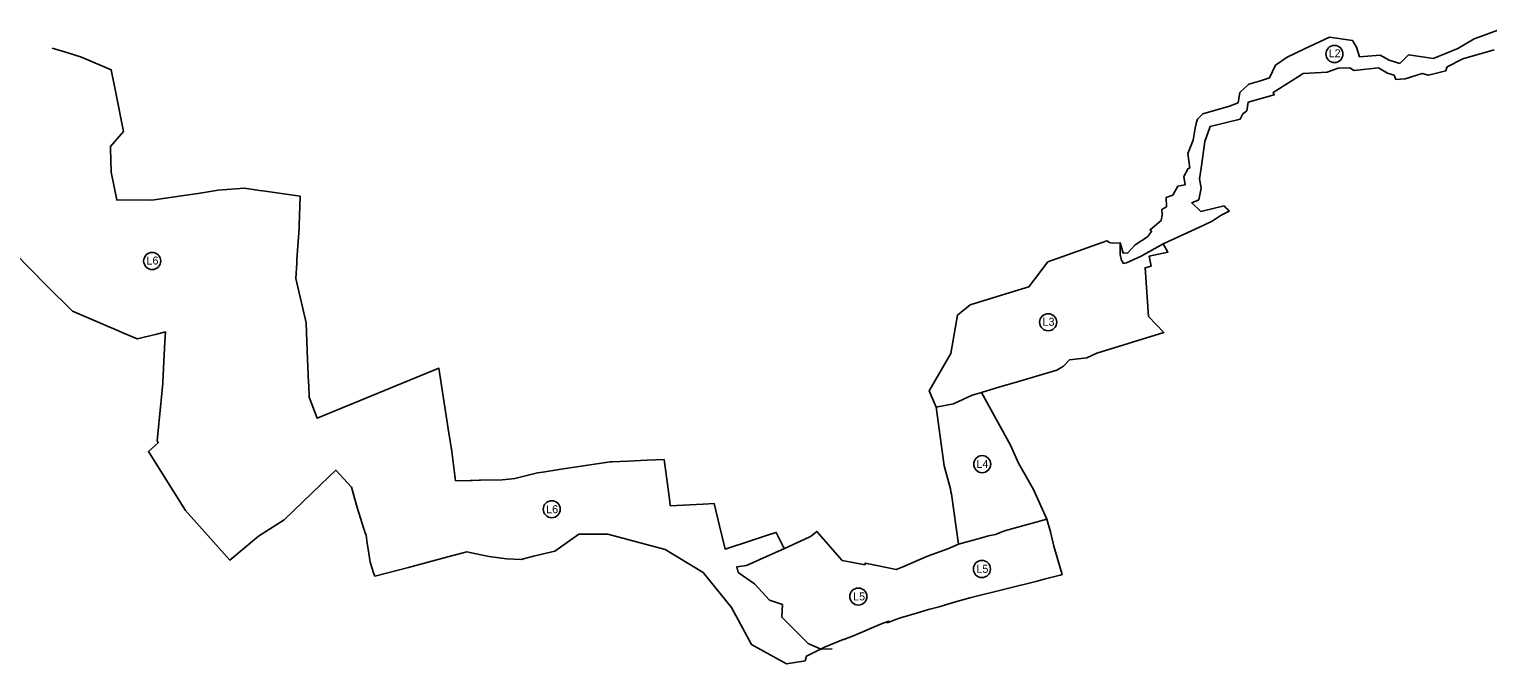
# Model space of a CAD drawing. Extents: x -445081 to -429827, y -1135509 to -1130100.
# Drawn here: x -443832 to -441644, y -1133014 to -1132062 of the extents above; entities that cross this region are included whole.
import ezdxf

# ---------------------------------------------------------------- set-up
doc = ezdxf.new("R2010")
doc.units = 0
for name, color, linetype in [('Vrstva 32', 7, 'Continuous'), ('Vrstva 33', 7, 'Continuous'), ('Vrstva 36', 7, 'Continuous')]:
    doc.layers.add(name, color=color, linetype=linetype)

msp = doc.modelspace()

# ---------------------------------------------------------------- linework, layer by layer
at = {"layer": 'Vrstva 32'}
for points in [[(-442481.7, -1132604.5), (-442471.3, -1132628.9), (-442445, -1132624.2), (-442417, -1132611.1), (-442403.3, -1132606.9), (-442375.6, -1132598.5), (-442355.9, -1132592.9), (-442352.4, -1132591.8), (-442289.9, -1132573.6), (-442280.2, -1132567.3), (-442271.2, -1132557.9), (-442244.9, -1132555), (-442229.9, -1132548), (-442129.4, -1132516.8), (-442152.4, -1132493.2), (-442157.6, -1132419.9), (-442148.6, -1132417.3), (-442151.5, -1132402.4), (-442123.4, -1132396.4), (-442130.5, -1132383.9), (-442163.5, -1132402.4), (-442185.4, -1132412.5), (-442190.7, -1132413.5), (-442190.7, -1132412.2), (-442193.2, -1132409.2), (-442195.3, -1132400), (-442195.2, -1132382.4), (-442206.9, -1132383.1), (-442211.2, -1132381.9), (-442215.2, -1132379.6), (-442303.5, -1132411.2), (-442331.9, -1132448.3), (-442353.4, -1132454.8), (-442420.1, -1132475.6), (-442439.3, -1132491), (-442442.6, -1132510.8), (-442449, -1132548.5), (-442481.7, -1132604.5)], [(-442285.2, -1132881.1), (-442281.9, -1132880.2), (-442294.6, -1132837.7), (-442299.5, -1132816), (-442304.9, -1132797), (-442368.8, -1132814.3), (-442381.9, -1132819.8), (-442392.6, -1132822.1), (-442404.6, -1132825.4), (-442437.4, -1132834.6), (-442453.6, -1132841.4), (-442484, -1132852.3), (-442499.3, -1132858.8), (-442519.7, -1132867.8), (-442531, -1132872.7), (-442562.6, -1132866.1), (-442577.8, -1132862.9), (-442577.7, -1132865.3), (-442612, -1132859.2), (-442612.8, -1132858.5), (-442649.9, -1132815.5), (-442657.9, -1132821.9), (-442661.6, -1132824.2), (-442698.6, -1132841), (-442735.4, -1132857.5), (-442755.4, -1132866.7), (-442770, -1132868.5), (-442768.2, -1132877), (-442743.8, -1132894.2), (-442720.9, -1132918.3), (-442701.6, -1132925.2), (-442702.7, -1132943.8), (-442663.1, -1132983.6), (-442643.9, -1132991.8), (-442643.5, -1132991.5), (-442639.5, -1132989.6), (-442638.7, -1132989.2), (-442610.4, -1132977.7), (-442609.9, -1132977.5), (-442609.4, -1132977.3), (-442596.7, -1132972.3), (-442581.2, -1132965.8), (-442568.4, -1132960.4), (-442553.3, -1132954.2), (-442551.9, -1132953.7), (-442542.3, -1132949.9), (-442544.6, -1132952.4), (-442540.7, -1132951), (-442532.9, -1132947.8), (-442524.4, -1132945.2), (-442497.2, -1132936.8), (-442487.8, -1132934.2), (-442480.6, -1132932.2), (-442466.4, -1132928.3), (-442445.5, -1132922.1), (-442420.8, -1132914.9), (-442364.2, -1132900.9), (-442319.8, -1132890.2), (-442309.1, -1132886.8), (-442285.2, -1132881.1)], [(-442281.9, -1132880.2), (-442294.6, -1132837.7), (-442299.5, -1132816), (-442304.9, -1132797), (-442368.8, -1132814.3), (-442381.9, -1132819.8), (-442392.6, -1132822.1), (-442404.6, -1132825.4), (-442437.4, -1132834.6), (-442453.6, -1132841.4), (-442484, -1132852.3), (-442499.3, -1132858.8), (-442519.7, -1132867.8), (-442531, -1132872.7), (-442562.6, -1132866.1), (-442577.8, -1132862.9), (-442577.7, -1132865.3), (-442612, -1132859.2), (-442612.8, -1132858.5), (-442649.9, -1132815.5), (-442657.9, -1132821.9), (-442661.6, -1132824.2), (-442698.6, -1132841), (-442735.4, -1132857.5), (-442755.4, -1132866.7), (-442770, -1132868.5), (-442768.2, -1132877), (-442743.8, -1132894.2), (-442720.9, -1132918.3), (-442701.6, -1132925.2), (-442702.7, -1132943.8), (-442663.1, -1132983.6), (-442643.9, -1132991.8), (-442627.1, -1132991.7)]]:
    msp.add_lwpolyline(points, dxfattribs=at)
msp.add_lwpolyline([(-442471.3, -1132628.9), (-442445, -1132624.2), (-442417, -1132611.1), (-442403.3, -1132606.9), (-442375.6, -1132598.5), (-442355.9, -1132592.9), (-442352.4, -1132591.8), (-442289.9, -1132573.6), (-442280.2, -1132567.3), (-442271.2, -1132557.9), (-442244.9, -1132555), (-442229.9, -1132548), (-442129.4, -1132516.8), (-442152.4, -1132493.2), (-442157.6, -1132419.9), (-442148.6, -1132417.3), (-442151.5, -1132402.4), (-442123.4, -1132396.4), (-442130.5, -1132383.9), (-442163.5, -1132402.4), (-442185.4, -1132412.5), (-442190.7, -1132413.5), (-442190.7, -1132412.2), (-442193.2, -1132409.2), (-442195.3, -1132400), (-442195.2, -1132382.4), (-442206.9, -1132383.1), (-442211.2, -1132381.9), (-442215.2, -1132379.6), (-442303.5, -1132411.2), (-442331.9, -1132448.3), (-442353.4, -1132454.8), (-442420.1, -1132475.6), (-442439.3, -1132491), (-442442.6, -1132510.8), (-442449, -1132548.5), (-442481.7, -1132604.5)], close=True, dxfattribs=at)
at = {"layer": 'Vrstva 33'}
for points in [[(-442195.2, -1132382.4), (-442190.8, -1132398), (-442183.7, -1132397.5), (-442172.8, -1132385.6), (-442154.2, -1132373.6), (-442148, -1132365.6), (-442150.2, -1132362.8), (-442133.8, -1132348.9), (-442132.2, -1132341.2), (-442132.5, -1132332.4), (-442125.6, -1132328.3), (-442125.9, -1132314.4), (-442116.1, -1132310.8), (-442108.8, -1132297.6), (-442097.4, -1132295.3), (-442099.4, -1132283.1), (-442093, -1132270.9), (-442090.7, -1132270.3), (-442093.5, -1132248.6), (-442085.7, -1132228.3), (-442082.6, -1132210.5), (-442081.2, -1132204), (-442080.9, -1132203.1), (-442079, -1132197.1), (-442071.1, -1132188.8), (-442031, -1132177.6), (-442020.8, -1132173.4), (-442018.2, -1132172.4), (-442015.5, -1132157.2), (-442008.1, -1132150.2), (-442002.2, -1132144.5), (-441984.5, -1132139.3), (-441971, -1132135.1), (-441961.9, -1132116.1), (-441944.5, -1132104), (-441918.4, -1132091.6), (-441881.2, -1132074), (-441846.7, -1132079.2), (-441840.4, -1132089.1), (-441835.9, -1132103.7), (-441805, -1132100.9), (-441791.6, -1132108.3), (-441775.4, -1132113.3), (-441764.7, -1132102.6), (-441762.5, -1132100.4), (-441738.5, -1132103.9), (-441725.7, -1132105.8), (-441708.3, -1132098.9), (-441688.7, -1132091), (-441666.7, -1132077.9), (-441664.3, -1132076.4), (-441645.9, -1132069.8), (-441624.7, -1132062.1)], [(-443797.2, -1132090.5), (-443775, -1132097.2), (-443752.8, -1132103.8), (-443708.3, -1132123), (-443701.6, -1132157.3), (-443690.1, -1132215.5), (-443709.7, -1132238.1), (-443709.6, -1132240.9), (-443708.5, -1132276.5), (-443700.2, -1132318.2), (-443647.6, -1132318.3), (-443595.9, -1132310.9), (-443574.9, -1132308), (-443548.1, -1132303.7), (-443508.6, -1132300.6), (-443485.9, -1132303.9), (-443480.9, -1132304.6), (-443424.8, -1132312.7), (-443426.5, -1132356.7), (-443426.7, -1132360.5), (-443429.9, -1132407.6), (-443430.2, -1132412.8), (-443431.6, -1132436.1), (-443416.2, -1132502.4), (-443414.4, -1132544.3), (-443412.3, -1132592.5), (-443412.1, -1132596.2), (-443411.4, -1132614.2), (-443399.4, -1132645.6), (-443217.1, -1132570.4), (-443203.2, -1132661.3), (-443197.8, -1132695.6), (-443192, -1132739.3), (-443170.3, -1132738.9), (-443166.8, -1132738.8), (-443156.6, -1132738.7), (-443154.5, -1132738.6), (-443122.1, -1132737.8), (-443112.2, -1132737.2), (-443102.9, -1132735.9), (-443069.3, -1132727.7), (-443060.9, -1132726.3), (-443033.6, -1132722), (-443013.6, -1132719), (-442959.9, -1132711), (-442957.4, -1132710.9), (-442932.9, -1132709.8), (-442905.3, -1132708.7), (-442892.3, -1132708.1), (-442879.1, -1132707.7), (-442870.8, -1132770.6), (-442870, -1132777), (-442820.5, -1132774.4), (-442803.9, -1132773.7), (-442796, -1132807.1), (-442787.8, -1132841.9), (-442746.7, -1132828.7), (-442721, -1132820), (-442711, -1132817), (-442700.1, -1132838.8), (-442698.6, -1132841)], [(-441634.2, -1132092.9), (-441681.1, -1132106.6), (-441704.8, -1132118.3), (-441705.6, -1132120.9), (-441706.8, -1132124.7), (-441732.8, -1132130.9), (-441742.3, -1132128.4), (-441767.7, -1132136.5), (-441781.4, -1132137.6), (-441784.3, -1132131), (-441794.2, -1132127.9), (-441807.8, -1132120.2), (-441844, -1132124.2), (-441845, -1132123.6), (-441850.5, -1132120.2), (-441867.9, -1132120.3), (-441884.5, -1132126.4), (-441920.6, -1132128.4), (-441927.8, -1132132.9), (-441965.5, -1132156.8), (-441964.2, -1132160.6), (-442003, -1132171.4), (-442005, -1132184.4), (-442011.2, -1132189.1), (-442014.9, -1132196.8), (-442060.1, -1132207.8), (-442068, -1132230.3), (-442073.7, -1132270.7), (-442076, -1132286.7), (-442073.8, -1132300.7), (-442077.1, -1132317.9), (-442087.8, -1132322.6), (-442074.1, -1132335.5), (-442039.2, -1132327), (-442036.4, -1132330), (-442033.8, -1132332.7), (-442031.5, -1132335.2), (-442043.8, -1132340.9), (-442057.2, -1132350.2), (-442076.1, -1132359), (-442130.5, -1132383.9)], [(-442643.9, -1132991.8), (-442648.5, -1132994), (-442665.8, -1133002.6), (-442666.7, -1133006), (-442667.6, -1133009.5), (-442695.7, -1133014), (-442748.2, -1132985.1), (-442778, -1132929.5), (-442820.7, -1132876.9), (-442877.4, -1132842.4), (-442963.8, -1132819.4), (-443007.1, -1132819.4), (-443043.3, -1132844.8), (-443075, -1132852.7), (-443090, -1132856.5), (-443093.3, -1132857.4), (-443115.4, -1132856.5), (-443141.4, -1132853.2), (-443154.2, -1132850.5), (-443175.1, -1132846), (-443203.5, -1132853.6), (-443262.8, -1132869.3), (-443313.1, -1132882.3), (-443314.3, -1132878.9), (-443320.2, -1132861.5), (-443323.1, -1132841.9), (-443324.4, -1132833.1), (-443326.2, -1132821.1), (-443327.8, -1132816.5), (-443328.6, -1132814), (-443329.8, -1132810.1), (-443339.3, -1132779.6), (-443347.9, -1132748.8), (-443371.7, -1132723.7), (-443393.8, -1132744.9), (-443449.2, -1132798.2), (-443487.4, -1132822.7), (-443530.3, -1132858.5), (-443597.1, -1132784.2), (-443652.7, -1132695.3), (-443642.4, -1132686.5), (-443637.8, -1132682.5), (-443639.5, -1132679.3), (-443633.8, -1132623.7), (-443632, -1132603.3), (-443631.2, -1132593.2), (-443630.5, -1132580.3), (-443627.8, -1132531.1), (-443627.2, -1132516.1), (-443639.9, -1132519.4), (-443669.4, -1132526.6), (-443688.6, -1132518.4), (-443707.8, -1132510.1), (-443712, -1132508.3), (-443721.1, -1132504.4), (-443766.5, -1132485.2), (-443805.3, -1132446.3), (-443853.4, -1132397.7)], [(-442403.3, -1132606.9), (-442373, -1132661.6), (-442359.8, -1132686.2), (-442347.6, -1132713), (-442325, -1132752.5), (-442304.9, -1132797)], [(-442437.4, -1132834.6), (-442448.2, -1132759.3), (-442449, -1132756.2), (-442449.4, -1132751.7), (-442459, -1132717.2), (-442471.3, -1132628.9)]]:
    msp.add_lwpolyline(points, dxfattribs=at)
at = {"layer": 'Vrstva 36'}
for centre in [(-441873.7, -1132099.3), (-443647, -1132409.8), (-442303.1, -1132501.7), (-442402, -1132714.5), (-443047.7, -1132782.1), (-442402.4, -1132871.8), (-442587.8, -1132913.1)]:
    msp.add_circle(centre, 12.8, dxfattribs=at)

# ---------------------------------------------------------------- texts
for s, p in [('L2', (-441882.3, -1132104.2)), ('L6', (-443655.5, -1132415.1)), ('L3', (-442311.4, -1132506.9)), ('L4', (-442410.6, -1132720.2)), ('L6', (-443056, -1132788.1)), ('L5', (-442410.6, -1132877.5)), ('L5', (-442595.5, -1132918.9))]:
    msp.add_text(s, height=12, dxfattribs=at).set_placement(p)

doc.saveas('drawing.dxf')
